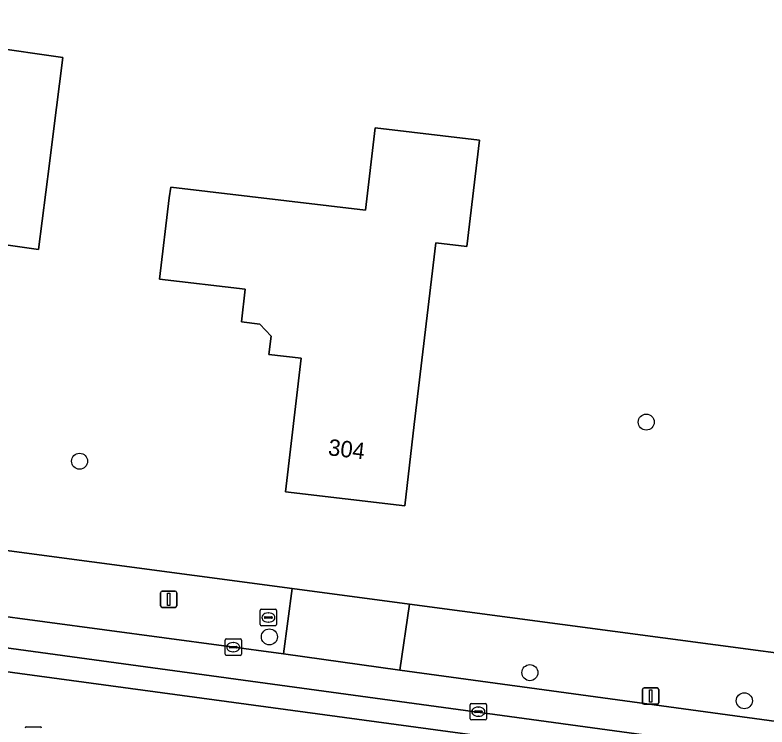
# Model space of a CAD drawing. Extents: x 161692 to 162379, y 380760 to 381678.
# Drawn here: x 161820.63 to 161866.5, y 380830.74 to 380874.19 of the extents above; entities that cross this region are included whole.
import ezdxf

# ---------------------------------------------------------------- set-up
doc = ezdxf.new("R2010")
doc.units = 0
for name, color, linetype in [('IMGEO_Boom', 7, 'Continuous'), ('IMGEO_Brandkraan', 7, 'Continuous'), ('IMGEO_Erf', 7, 'Continuous'), ('IMGEO_Kolk', 7, 'Continuous'), ('IMGEO_Lichtmast', 7, 'Continuous'), ('IMGEO_Pand', 7, 'Continuous'), ('IMGEO_Pand_nummerreeks', 7, 'Continuous'), ('IMGEO_Parkeervlak_open', 7, 'Continuous'), ('IMGEO_Rijbaan_lokaal_gesloten', 7, 'Continuous'), ('IMGEO_Voetpad_open', 7, 'Continuous')]:
    doc.layers.add(name, color=color, linetype=linetype)

msp = doc.modelspace()

# ---------------------------------------------------------------- linework, layer by layer
at = {"layer": 'IMGEO_Boom'}
for centre in [(161859.132, 380849.347), (161824.562, 380846.962), (161836.141, 380836.243), (161852.031, 380834.058), (161865.114, 380832.343)]:
    msp.add_circle(centre, 0.489, dxfattribs=at)
at = {"layer": 'IMGEO_Brandkraan'}
for p, q in [((161835.579, 380836.999), (161835.579, 380837.851)), ((161835.654, 380837.925), (161836.506, 380837.925)), ((161836.58, 380837.851), (161836.58, 380836.999)), ((161835.838, 380837.419), (161835.838, 380837.431)), ((161836.276, 380837.382), (161835.878, 380837.382)), ((161835.881, 380837.468), (161836.279, 380837.468)), ((161836.067, 380837.705), (161836.092, 380837.705)), ((161836.322, 380837.431), (161836.322, 380837.419)), ((161836.506, 380836.925), (161835.654, 380836.925)), ((161836.09, 380837.145), (161836.065, 380837.145))]:
    msp.add_line(p, q, dxfattribs=at)
for points in [[(161835.579, 380836.999), (161835.579, 380837.851)], [(161835.654, 380837.925), (161836.506, 380837.925)], [(161836.58, 380837.851), (161836.58, 380836.999)], [(161836.506, 380836.925), (161835.654, 380836.925)]]:
    msp.add_lwpolyline(points, dxfattribs=at)
for centre, radius, start, end in [((161835.656, 380837.849), 0.0765, 91.552, 178.448), ((161835.656, 380837.849), 0.0765, 91.552, 178.448), ((161836.504, 380837.849), 0.0765, 1.552, 88.448), ((161836.504, 380837.849), 0.0765, 1.552, 88.448), ((161835.878, 380837.428), 0.0403, 85.8775, 175.7526), ((161835.875, 380837.418), 0.0366, 178.938, 274.7102), ((161836.279, 380837.425), 0.043, 264.8664, 352.4533), ((161836.283, 380837.43), 0.0386, 1.7309, 96.639), ((161835.656, 380837.001), 0.0765, 181.552, 268.448), ((161835.656, 380837.001), 0.0765, 181.552, 268.448), ((161836.504, 380837.001), 0.0765, 271.552, 358.448), ((161836.504, 380837.001), 0.0765, 271.552, 358.448)]:
    msp.add_arc(centre, radius, start, end, dxfattribs=at)
for centre, major_axis, ratio, start_param, end_param in [((161836.066, 380837.425), (-0.387, 0.002), 0.722429, 4.712389, 7.853982), ((161836.091, 380837.425), (-0.39, 0.002), 0.717154, 1.570796, 4.712389)]:
    msp.add_ellipse(centre, major_axis=major_axis, ratio=ratio, start_param=start_param, end_param=end_param, dxfattribs=at)
at = {"layer": 'IMGEO_Erf'}
msp.add_lwpolyline([(161819.323, 380841.622), (161837.528, 380839.198), (161844.689, 380838.245), (161888.15, 380832.459), (161889.139, 380832.444), (161889.404, 380832.497), (161889.663, 380832.572), (161889.914, 380832.671), (161890.155, 380832.791), (161890.385, 380832.933), (161890.601, 380833.094), (161890.802, 380833.275), (161890.986, 380833.472), (161891.151, 380833.685), (161891.297, 380833.912), (161891.422, 380834.151), (161891.525, 380834.4), (161891.605, 380834.658), (161891.663, 380834.922), (161891.696, 380835.189), (161891.703, 380835.311), (161897.898, 380881.646)], dxfattribs=at)
for points in [[(161823.551, 380871.601), (161822.959, 380866.935), (161822.73, 380865.13), (161822.065, 380859.887), (161817.499, 380860.537), (161818.165, 380865.78), (161818.987, 380872.251)], [(161848.951, 380866.551), (161848.183, 380860.054), (161846.292, 380860.277), (161844.983, 380849.202), (161844.396, 380844.236), (161837.124, 380845.096), (161838.088, 380853.24), (161836.112, 380853.474), (161836.245, 380854.598), (161835.558, 380855.329), (161834.435, 380855.461), (161834.671, 380857.457), (161829.448, 380858.074), (161830.036, 380863.04), (161830.139, 380863.678), (161842.011, 380862.277), (161842.604, 380867.299)]]:
    msp.add_lwpolyline(points, close=True, dxfattribs=at)
at = {"layer": 'IMGEO_Kolk'}
for p, q in [((161833.436, 380835.189), (161833.436, 380836.041)), ((161833.511, 380836.115), (161834.363, 380836.115)), ((161834.437, 380836.041), (161834.437, 380835.189)), ((161833.695, 380835.609), (161833.695, 380835.621)), ((161834.133, 380835.572), (161833.735, 380835.572)), ((161833.738, 380835.658), (161834.136, 380835.658)), ((161833.924, 380835.895), (161833.949, 380835.895)), ((161834.179, 380835.621), (161834.179, 380835.609)), ((161834.363, 380835.115), (161833.511, 380835.115)), ((161833.947, 380835.335), (161833.922, 380835.335)), ((161848.386, 380831.25), (161848.386, 380832.102)), ((161848.461, 380832.176), (161849.313, 380832.176)), ((161848.874, 380831.956), (161848.899, 380831.956)), ((161849.387, 380832.102), (161849.387, 380831.25)), ((161848.645, 380831.67), (161848.645, 380831.682)), ((161849.083, 380831.633), (161848.685, 380831.633)), ((161848.688, 380831.719), (161849.086, 380831.719)), ((161848.897, 380831.396), (161848.872, 380831.396)), ((161849.129, 380831.682), (161849.129, 380831.67)), ((161849.313, 380831.176), (161848.461, 380831.176)), ((161821.323, 380830.744), (161822.175, 380830.744))]:
    msp.add_line(p, q, dxfattribs=at)
for points in [[(161833.436, 380835.189), (161833.436, 380836.041)], [(161833.511, 380836.115), (161834.363, 380836.115)], [(161834.437, 380836.041), (161834.437, 380835.189)], [(161834.363, 380835.115), (161833.511, 380835.115)], [(161848.386, 380831.25), (161848.386, 380832.102)], [(161848.461, 380832.176), (161849.313, 380832.176)], [(161849.387, 380832.102), (161849.387, 380831.25)], [(161849.313, 380831.176), (161848.461, 380831.176)], [(161821.323, 380830.744), (161822.175, 380830.744)]]:
    msp.add_lwpolyline(points, dxfattribs=at)
for centre, radius, start, end in [((161833.513, 380836.039), 0.0765, 91.552, 178.448), ((161833.513, 380836.039), 0.0765, 91.552, 178.448), ((161834.361, 380836.039), 0.0765, 1.552, 88.448), ((161834.361, 380836.039), 0.0765, 1.552, 88.448), ((161833.735, 380835.618), 0.0403, 85.8775, 175.7526), ((161833.732, 380835.608), 0.0366, 178.938, 274.7102), ((161834.136, 380835.615), 0.043, 264.8664, 352.4533), ((161834.14, 380835.62), 0.0386, 1.7309, 96.639), ((161833.513, 380835.191), 0.0765, 181.552, 268.448), ((161833.513, 380835.191), 0.0765, 181.552, 268.448), ((161834.361, 380835.191), 0.0765, 271.552, 358.448), ((161834.361, 380835.191), 0.0765, 271.552, 358.448), ((161848.463, 380832.1), 0.0765, 91.552, 178.448), ((161848.463, 380832.1), 0.0765, 91.552, 178.448), ((161849.311, 380832.1), 0.0765, 1.552, 88.448), ((161849.311, 380832.1), 0.0765, 1.552, 88.448), ((161848.685, 380831.679), 0.0403, 85.8775, 175.7526), ((161848.682, 380831.669), 0.0366, 178.938, 274.7102), ((161849.086, 380831.676), 0.043, 264.8664, 352.4533), ((161849.09, 380831.681), 0.0386, 1.7309, 96.639), ((161848.463, 380831.252), 0.0765, 181.552, 268.448), ((161848.463, 380831.252), 0.0765, 181.552, 268.448), ((161849.311, 380831.252), 0.0765, 271.552, 358.448), ((161849.311, 380831.252), 0.0765, 271.552, 358.448), ((161821.325, 380830.668), 0.0765, 91.552, 178.448), ((161821.325, 380830.668), 0.0765, 91.552, 178.448), ((161822.173, 380830.668), 0.0765, 1.552, 88.448), ((161822.173, 380830.668), 0.0765, 1.552, 88.448)]:
    msp.add_arc(centre, radius, start, end, dxfattribs=at)
for centre, major_axis, ratio, start_param, end_param in [((161833.923, 380835.615), (-0.387, 0.002), 0.722429, 4.712389, 7.853982), ((161833.948, 380835.615), (-0.39, 0.002), 0.717154, 1.570796, 4.712389), ((161848.873, 380831.676), (-0.387, 0.002), 0.722429, 4.712389, 7.853982), ((161848.898, 380831.676), (-0.39, 0.002), 0.717154, 1.570796, 4.712389)]:
    msp.add_ellipse(centre, major_axis=major_axis, ratio=ratio, start_param=start_param, end_param=end_param, dxfattribs=at)
at = {"layer": 'IMGEO_Lichtmast'}
for p, q in [((161829.501, 380838.137), (161829.501, 380838.937)), ((161829.501, 380838.937), (161829.501, 380838.137)), ((161829.601, 380839.037), (161830.391, 380839.037)), ((161830.391, 380839.037), (161829.601, 380839.037)), ((161830.491, 380838.937), (161830.491, 380838.137)), ((161830.491, 380838.137), (161830.491, 380838.937)), ((161830.391, 380838.037), (161829.601, 380838.037)), ((161829.601, 380838.037), (161830.391, 380838.037)), ((161858.903, 380832.226), (161858.903, 380833.026)), ((161858.903, 380833.026), (161858.903, 380832.226)), ((161859.003, 380833.126), (161859.793, 380833.126)), ((161859.793, 380833.126), (161859.003, 380833.126)), ((161859.893, 380833.026), (161859.893, 380832.226)), ((161859.893, 380832.226), (161859.893, 380833.026)), ((161859.793, 380832.126), (161859.003, 380832.126)), ((161859.003, 380832.126), (161859.793, 380832.126))]:
    msp.add_line(p, q, dxfattribs=at)
for points in [[(161829.921, 380838.912), (161830.071, 380838.912), (161830.071, 380838.162), (161829.921, 380838.162), (161829.921, 380838.912)], [(161859.323, 380833.001), (161859.473, 380833.001), (161859.473, 380832.251), (161859.323, 380832.251), (161859.323, 380833.001)]]:
    msp.add_lwpolyline(points, dxfattribs=at)
for centre, start, end in [((161829.601, 380838.937), 90, 180), ((161829.601, 380838.937), 90, 180), ((161830.391, 380838.937), 0, 90), ((161830.391, 380838.937), 360, 90), ((161829.601, 380838.137), 180, 270), ((161829.601, 380838.137), 180, 270), ((161830.391, 380838.137), 270, 0), ((161830.391, 380838.137), 270, 0), ((161859.003, 380833.026), 90, 180), ((161859.003, 380833.026), 90, 180), ((161859.793, 380833.026), 0, 90), ((161859.793, 380833.026), 360, 90), ((161859.003, 380832.226), 180, 270), ((161859.003, 380832.226), 180, 270), ((161859.793, 380832.226), 270, 0), ((161859.793, 380832.226), 270, 0)]:
    msp.add_arc(centre, 0.1, start, end, dxfattribs=at)
at = {"layer": 'IMGEO_Pand'}
for points in [[(161823.551, 380871.601), (161818.987, 380872.251), (161818.165, 380865.78), (161817.499, 380860.537), (161822.065, 380859.887), (161822.73, 380865.13), (161822.959, 380866.935)], [(161844.983, 380849.202), (161846.292, 380860.277), (161848.183, 380860.054), (161848.951, 380866.551), (161842.604, 380867.299), (161842.011, 380862.277), (161830.139, 380863.678), (161830.036, 380863.04), (161829.448, 380858.074), (161834.671, 380857.457), (161834.435, 380855.461), (161835.558, 380855.329), (161836.245, 380854.598), (161836.112, 380853.474), (161838.088, 380853.24), (161837.124, 380845.096), (161844.396, 380844.236)]]:
    msp.add_lwpolyline(points, close=True, dxfattribs=at)
at = {"layer": 'IMGEO_Parkeervlak_open'}
msp.add_lwpolyline([(161886.625, 380828.406), (161844.094, 380834.202), (161836.995, 380835.21), (161818.781, 380837.656), (161818.579, 380835.777), (161889.378, 380826.116)], dxfattribs=at)
at = {"layer": 'IMGEO_Rijbaan_lokaal_gesloten'}
for points in [[(161889.378, 380826.116), (161818.579, 380835.777)], [(161814.137, 380834.931), (162153.114, 380788.982), (162173.589, 380787.538), (162178.941, 380786.895), (162192.055, 380785.129), (162226.418, 380780.403), (162229.289, 380780.178), (162234.771, 380780.432)], [(162234.785, 380779.843), (162234.771, 380780.432), (162229.289, 380780.178), (162226.418, 380780.403), (162192.055, 380785.129), (162178.941, 380786.895), (162173.589, 380787.538), (162153.114, 380788.982), (161814.137, 380834.931)]]:
    msp.add_lwpolyline(points, dxfattribs=at)
at = {"layer": 'IMGEO_Voetpad_open'}
for points in [[(161819.323, 380841.622), (161819.348, 380841.407), (161818.146, 380841.574), (161817.665, 380837.832), (161818.781, 380837.656), (161836.995, 380835.21), (161837.528, 380839.198)], [(161837.528, 380839.198), (161836.995, 380835.21), (161844.094, 380834.202), (161844.689, 380838.245)]]:
    msp.add_lwpolyline(points, close=True, dxfattribs=at)
msp.add_lwpolyline([(161901.878, 380831.597), (161898.276, 380831.581), (161894.983, 380832.038), (161889.111, 380832.366), (161888.15, 380832.459), (161844.689, 380838.245), (161844.094, 380834.202), (161886.625, 380828.406)], dxfattribs=at)

# ---------------------------------------------------------------- texts
at = {"layer": 'IMGEO_Pand_nummerreeks'}
msp.add_text('304', height=1, rotation=353.2554, dxfattribs=at).set_placement((161839.688, 380847.331))

doc.saveas('drawing.dxf')
